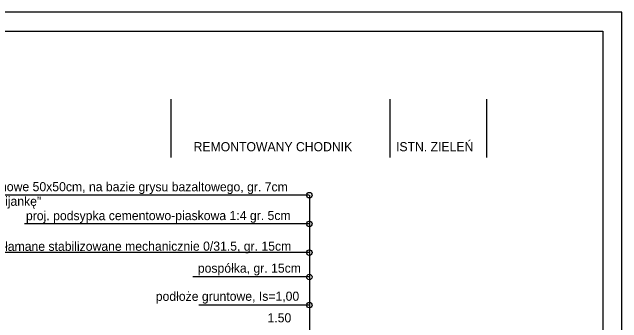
# Model space of a CAD drawing. Extents: x -219625893 to 7498339, y 5791790 to 5792761.
# Drawn here: x 7495443.7 to 7495527.2, y 5791896 to 5791938.5 of the extents above; entities that cross this region are included whole.
import ezdxf

# ---------------------------------------------------------------- set-up
doc = ezdxf.new("R2010")
doc.units = 0
for name, color, linetype in [('D_OPISY', 7, 'Continuous'), ('D_robocze_1', 7, 'Continuous'), ('D_wymiary_500', 7, 'Continuous'), ('Level 10', 7, 'Continuous'), ('wymiary', 7, 'Continuous')]:
    doc.layers.add(name, color=color, linetype=linetype)

msp = doc.modelspace()

# ---------------------------------------------------------------- linework, layer by layer
at = {"layer": 'D_robocze_1'}
for p, q in [((7495484.431, 5791913.423), (7495431.039, 5791913.423)), ((7495484.443, 5791913.427), (7495484.443, 5791866.18)), ((7495484.431, 5791909.495), (7495445.397, 5791909.495)), ((7495484.431, 5791905.566), (7495435.1, 5791905.566))]:
    msp.add_line(p, q, dxfattribs=at)
at = {"layer": 'Level 10'}
for p, q in [((7495527.248, 5791938.455), (7495127.248, 5791938.455)), ((7495527.248, 5791789.955), (7495527.248, 5791938.455)), ((7495142.248, 5791935.855), (7495524.648, 5791935.855)), ((7495524.648, 5791935.855), (7495524.648, 5791792.555))]:
    msp.add_line(p, q, dxfattribs=at)
at = {"layer": 'wymiary'}
for p, q in [((7495465.458, 5791926.549), (7495465.458, 5791918.561)), ((7495495.458, 5791926.549), (7495495.458, 5791918.561)), ((7495508.711, 5791926.549), (7495508.711, 5791918.561))]:
    msp.add_line(p, q, dxfattribs=at)
for points in [[(7495484.443, 5791902.231), (7495468.487, 5791902.231)], [(7495484.443, 5791898.384), (7495469.291, 5791898.384)]]:
    msp.add_lwpolyline(points, dxfattribs=at)
for centre in [(7495484.432, 5791913.423), (7495484.432, 5791909.495), (7495484.432, 5791905.566), (7495484.443, 5791902.231), (7495484.443, 5791898.384)]:
    msp.add_circle(centre, 0.375, dxfattribs=at)

# ---------------------------------------------------------------- texts
at = {"layer": 'D_OPISY'}
for s, p in [('REMONTOWANY CHODNIK', (7495468.582, 5791919.43)), ('ISTN. ZIELEŃ', (7495496.317, 5791919.43))]:
    msp.add_text(s, height=1.25, dxfattribs=at).set_placement(p)
at = {"layer": 'D_wymiary_500'}
msp.add_text('1.50', height=1.25, dxfattribs=at).set_placement((7495478.708, 5791896.018))
at = {"layer": 'wymiary'}
for s, height, rotation, p in [('proj. płyty betonowe 50x50cm, na bazie grysu bazaltowego, gr. 7cm', 1.25089, 359.95715, (7495431.18, 5791913.977)), ('układane na "mijankę"', 1.25089, 359.95715, (7495431.18, 5791911.979)), ('proj. podsypka cementowo-piaskowa 1:4 gr. 5cm', 1.25089, 0.04285, (7495445.613, 5791909.993)), ('kruszywo łamane stabilizowane mechanicznie 0/31.5, gr. 15cm', 1.25, 0.04925, (7495435.319, 5791905.792)), ('pospółka, gr. 15cm', 1.25, 0.04925, (7495469.162, 5791902.811)), ('podłoże gruntowe, Is=1,00', 1.25, 0.04925, (7495463.397, 5791898.958))]:
    msp.add_text(s, height=height, rotation=rotation, dxfattribs=at).set_placement(p)

doc.saveas('drawing.dxf')
